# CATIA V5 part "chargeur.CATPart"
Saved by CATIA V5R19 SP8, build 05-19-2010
Part number: chargeur 
Material "Plexiglas": density 1200 kg/m3, Young's modulus 2.9e+09 Pa, Poisson ratio 0.4, thermal expansion 7e-05 1/K
Bounding box of the stored display mesh (mm): x 0 to 52.342, y 0 to 26, z -99.185 to 5
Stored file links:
  E:\Catia parts\GLOCK\chargeur.CATPart
  D:\catia\intel_a\startup\materials\French\Catalog.CATMaterial
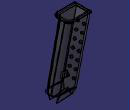
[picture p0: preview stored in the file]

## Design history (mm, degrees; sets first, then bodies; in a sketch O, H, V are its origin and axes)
Body1 (main body)
  Solid1: solid without history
